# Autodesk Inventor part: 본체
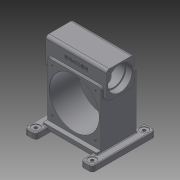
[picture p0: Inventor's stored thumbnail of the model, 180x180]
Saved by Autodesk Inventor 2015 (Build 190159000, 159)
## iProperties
Created: 2025-06
Part Number: 본체
Material: 일반
Document SubType Name: Modeling
Designer: User
Density: 1 g/cm^3
Appearance: 기본값
Mass: 2964.14 g
Surface Area: 3446.16 cm^2
Volume: 2964.14 cm^3
Author: User
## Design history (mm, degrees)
sketch "스케치1"
  geometry: L1 (-93, 103)-(93, 103); L2 (93, 103)-(93, -103); L3 (93, -103)-(-93, -103); L4 (-93, -103)-(-93, 103); L5 (-93, 103)-(93, -103); L6 (93, 103)-(-93, -103); 1 further point
  constraints: 12 end point, 2 midpoint, 2 parallel, 1 horizontal, 1 perpendicular
  dimensions: "d0" = 186 distance of L2.end L3.end; "d1" = 206 distance of L1.end L2.end
extrude "돌출1" new body sketch "스케치1" stored distance "d2" = 140; taper "d3" = 0 deg
sketch "스케치3"
  geometry: L1 (0, 0)-(186, 0) reference; L2 (186, -140)-(0, -140) reference; L3 (201, -180)-(181, -180); L4 (171, -170)-(171, 30); L5 (181, 40)-(201, 40); L6 (211, 30)-(211, -170); L7 (93, -140)-(93, 0); L8 (15, -170)-(15, 30); L9 (-25, 30)-(-25, -170); L10 (-15, -180)-(5, -180); L11 (5, 40)-(-15, 40); A1 r 10 centre (201, -170) between (201, -180) and (211, -170); A2 r 10 centre (181, -170) between (171, -170) and (181, -180); A3 r 10 centre (201, 30) between (211, 30) and (201, 40); A4 r 10 centre (181, 30) between (181, 40) and (171, 30); A5 r 10 centre (-15, -170) between (-25, -170) and (-15, -180); A6 r 10 centre (5, -170) between (5, -180) and (15, -170); A7 r 10 centre (5, 30) between (15, 30) and (5, 40); A8 r 10 centre (-15, 30) between (-15, 40) and (-25, 30); 4 further points
  constraints: 18 end point, 16 point on circle, 13 symmetric about line, 8 centre point, 8 tangent, 4 midpoint, 3 equal radius, 2 parallel, 1 horizontal, 1 horizontal alignment, 1 perpendicular, 4 other
  dimensions: "d4" = 10 radius of A1; "d5" = 40 distance between parallel lines of L4 L6; "d6" = 118 distance from line of point (93, -70) L6; "d7" = 220 distance between parallel lines of L5 L3
extrude "돌출2" join sketch "스케치3" stored distance "d8" = 20; taper "d9" = 0 deg
sketch "스케치4"
  geometry: L1 (-211, -170)-(-211, 30) reference; L2 (-201, 40)-(-181, 40) reference; L3 (-171, 30)-(-171, 0) reference; L4 (-186, 0)-(-171, 0) reference; L5 (-186, -140)-(-186, 0) reference; L6 (-171, -140)-(-186, -140) reference; L7 (-15, -140)-(-171, -140) reference; L8 (-15, -170)-(-15, -140) reference; L9 (15, -180)-(-5, -180) reference; L10 (25, 30)-(25, -170) reference; L11 (-5, 40)-(15, 40) reference; L12 (-15, 0)-(-15, 30) reference; L13 (-15, 0)-(0, 0) reference; L14 (0, 0)-(0, -140) reference; L15 (0, -140)-(-15, -140) reference; L16 (-181, -180)-(-201, -180) reference; L17 (-171, -140)-(-171, -170) reference; L18 (-171, 0)-(-15, 0) reference; A1 r 10 centre (-201, -170) between (-211, -170) and (-201, -180) reference; A2 r 10 centre (-201, 30) between (-201, 40) and (-211, 30) reference; A3 r 10 centre (-181, 30) between (-171, 30) and (-181, 40) reference; A4 r 10 centre (-5, -170) between (-15, -170) and (-5, -180) reference; A5 r 10 centre (15, -170) between (15, -180) and (25, -170) reference; A6 r 10 centre (15, 30) between (25, 30) and (15, 40) reference; A7 r 10 centre (-5, 30) between (-5, 40) and (-15, 30) reference; A8 r 10 centre (-181, -170) between (-181, -180) and (-171, -170) reference; 5 further points
  constraints: 2 vertical alignment, 1 horizontal alignment
  dimensions: "d10" = 196 distance of point (5, 20) point (-191, 20); "d11" = 20 distance from line of point (5, 20) L12; "d12" = 180 distance of point (5, 20) point (5, -160); "d13" = 180 distance of point (-191, -160) point (-191, 20); "d14" = 90 vertical distance of point (5, 20) point (-93, -70)
hole "구멍1" sketch "스케치4" at (-191, -160), (-191, 20), (5, 20), (5, -160) diameter "d15" = 11; stored, may be unused: countersink angle "d19" = 90 deg, drill point angle "d21" = 118 deg; dims "d16" = 6, "d17" = 28, "d18" = 2, "d20" = 8
sketch "스케치5"
  geometry: L1 (93, -93)-(93, 103) reference; L2 (93, 103)-(-93, 103) reference; L3 (-93, 103)-(-93, -93) reference; L4 (-93, -86)-(93, -86); 1 further point
  constraints: 2 end point, 2 point on line, 1 perpendicular
  dimensions: "d22" = 189 distance between parallel lines of L4 L2
extrude "돌출3" cut sketch "스케치5" distance "d23" = 15; taper "d24" = 0 deg
sketch "스케치6"
  geometry: L1 (-70, -86)-(-55, -86) reference; L2 (-55, -86)-(-55, 103) reference; L3 (-55, 103)-(70, 103) reference; L4 (70, 103)-(70, -103) reference; L5 (70, -103)-(-70, -103) reference; L6 (-70, -103)-(-70, -86) reference; L7 (-38, 158)-(38, 158); L8 (48, 148)-(48, 72); L9 (38, 62)-(-38, 62); L10 (-48, 72)-(-48, 148); L11 (100, -113)-(-100, -113) reference; A1 r 10 centre (-38, 148) between (-38, 158) and (-48, 148); A2 r 10 centre (38, 148) between (48, 148) and (38, 158); A3 r 10 centre (38, 72) between (38, 62) and (48, 72); A4 r 10 centre (-38, 72) between (-48, 72) and (-38, 62); 6 further points
  constraints: 8 end point, 8 point on circle, 8 point on line, 8 tangent, 4 centre point, 3 equal radius, 2 parallel, 1 horizontal, 1 midpoint, 1 perpendicular, 1 vertical alignment
  dimensions: "d32" = 10 radius of A1; "d33" = 96 distance between parallel lines of L8 L10; "d34" = 96 distance between parallel lines of L9 L7; "d47" = 175 distance between parallel lines of L11 L9
extrude "돌출4" join sketch "스케치6" stored distance "d30" = 210; taper "d31" = 0 deg
sketch "스케치7"
  geometry: L1 (-88, -113)-(-108, -113) reference; C1 r 86 at (0, 10); 1 further point
  constraints: 1 centre point, 1 vertical alignment
  dimensions: "d35" = 172 diameter of C1; "d36" = 123 distance from line of L1 C1.centre
extrude "돌출5" cut sketch "스케치7" distance "d37" = 102; taper "d38" = 0 deg
sketch "스케치8"
  geometry: C1 r 86 at (0, 0) reference; 1 further point
hole "구멍2" sketch "스케치8" at (0, 0) diameter "d39" = 54; stored, may be unused: countersink angle "d43" = 90 deg, drill point angle "d45" = 0 deg; dims "d40" = 6, "d41" = 62, "d42" = 16, "d44" = 19
sketch "스케치9"
  geometry: L1 (76, 47)-(-96, 47) reference; L2 (76, -55)-(-96, -55) reference; L3 (76, -55)-(-96, -55) reference; L4 (86, -55)-(-103, -55) reference; L5 (-103, -55)-(86, -55) reference; L6 (21, 47)-(-41, 47) reference; L7 (76, 47)-(-96, 47) reference; L8 (76, -55)-(-96, -55) reference; L9 (113, 100)-(113, -100) reference; 2 further points
  constraints: 1 horizontal alignment
  dimensions: "d46" = 223 distance from line of L9 point (-110, 0)
hole "구멍3" sketch "스케치9" at (-110, 0) diameter "d48" = 77; stored, may be unused: countersink angle "d52" = 90 deg, drill point angle "d54" = 0 deg; dims "d49" = 6, "d50" = 85, "d51" = 23, "d53" = 19
sketch "스케치10"
  geometry: C1 r 38.5 at (110, 0) reference; C2 r 42.5 at (110, 0); 1 further point
  constraints: 1 centre point, 1 coincident
  dimensions: "d55" = 85 diameter of C2
extrude "돌출6" cut sketch "스케치10" distance "d56" = 23; taper "d57" = 0 deg
fillet "모깎기1" dims "d58" = 10
sketch "스케치11"
  geometry: C1 r 86 at (0, 10) reference; 5 further points
  constraints: 2 horizontal alignment, 2 vertical alignment
  dimensions: "d59" = 150 distance of point (75, 85) point (-75, 85); "d60" = 150 distance of point (75, -65) point (75, 85); "d61" = 75 horizontal distance of point (75, 85) C1.centre; "d62" = 75 horizontal distance of point (75, 85) C1.centre
hole "구멍4" sketch "스케치11" at (-75, -65), (75, -65), (75, 85), (-75, 85) diameter "d63" = 6.647; stored, may be unused: countersink angle "d67" = 90 deg, drill point angle "d69" = 118 deg; dims "d64" = 16, "d65" = 85, "d66" = 23, "d68" = 18
sketch "스케치12"
  geometry: A1 r 10 centre (-148, -38) between (-158, -38) and (-148, -48) reference; A2 r 10 centre (-72, -38) between (-72, -48) and (-62, -38) reference; A3 r 10 centre (-72, 38) between (-62, 38) and (-72, 48) reference; A4 r 10 centre (-148, 38) between (-148, 48) and (-158, 38) reference; 1 further point
hole "구멍5" sketch "스케치12" at (-148, -38), (-148, 38), (-72, 38), (-72, -38) diameter "d70" = 4.917; stored, may be unused: countersink angle "d74" = 90 deg, drill point angle "d76" = 118 deg; dims "d71" = 12, "d72" = 85, "d73" = 23, "d75" = 14
sketch "스케치13"
  geometry: A1 r 10 centre (148, 38) between (158, 38) and (148, 48) reference; A2 r 10 centre (72, 38) between (72, 48) and (62, 38) reference; A3 r 10 centre (72, -38) between (62, -38) and (72, -48) reference; A4 r 10 centre (148, -38) between (148, -48) and (158, -38) reference; 1 further point
hole "구멍6" sketch "스케치13" at (148, -38), (148, 38), (72, 38), (72, -38) diameter "d77" = 4.917; stored, may be unused: countersink angle "d81" = 90 deg, drill point angle "d83" = 118 deg; dims "d78" = 12, "d79" = 85, "d80" = 23, "d82" = 14
sketch "스케치14"
  geometry: L1 (0, 10)-(210, 10) reference; 2 further points
  constraints: 1 vertical alignment, 1 other
  dimensions: "d84" = 30 distance from line of point (105, -20) L1
feature "엠보싱1" sketch "스케치14" dims "d0" = 186, "d1" = 206, "d4" = 10, "d5" = 40, "d6" = 118, "d7" = 220, "d85" = 0.5, "d86" = 0
fillet "모깎기2" dims "d87" = 3
fillet "모깎기3" dims "d88" = 3
fillet "모깎기4" dims "d89" = 1
chamfer "모따기1" distance "d90" = 1; stored, may be unused: second distance "d91" = 2, angle "d92" = 45 deg
fillet "모깎기5" dims "d93" = 1.1
node "솔리드1"
node "투영된 루프1"
node "투영된 루프2"
node "투영된 루프3"
node "절단 모서리 투영2"
node "절단 모서리 투영3"
